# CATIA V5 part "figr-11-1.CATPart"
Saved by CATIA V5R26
Part number: Part1
Bounding box of the stored display mesh (mm): x -50 to 50, y -98.731 to 72.975, z 0 to 120
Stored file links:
  D:\_Deepak\CATIA\CATIA V5-6R2016_Deepak\Resources\Part files\Partfiles\c11_catia_v5_6r2016_prt\figr-11-1.CATPart
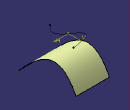
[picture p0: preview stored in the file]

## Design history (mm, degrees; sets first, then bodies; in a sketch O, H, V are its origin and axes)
Set1
  Sketch1 on yz-plane, origin (0, 0, 0), H (0, 1, 0), V (0, 0, 1)
    spline S1 through (-98.7309, 0) (-73.2816, 27.1192) (0, 74.8227) (72.975, 18.624)
    point P1 (-98.7309, 0)
    point P2 (0, 74.8227)
    coincidence: P1 H, P2 V
  Extrude1: Element1 Sketch1, Lim1 50, Lim2 50, Direction yz-plane
  Plane1: type Offset, RefPlane xy-plane, Offset 120
  Sketch2 on Plane1, origin (0, 0, 120), H (1, 0, 0), V (0, 1, 0)
    spline S1 through (28.7787, 44.6229) (-22.3035, 19.7059) (20.5049, -22.8447) (5.396, -48.9118)
Body1 (main body)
